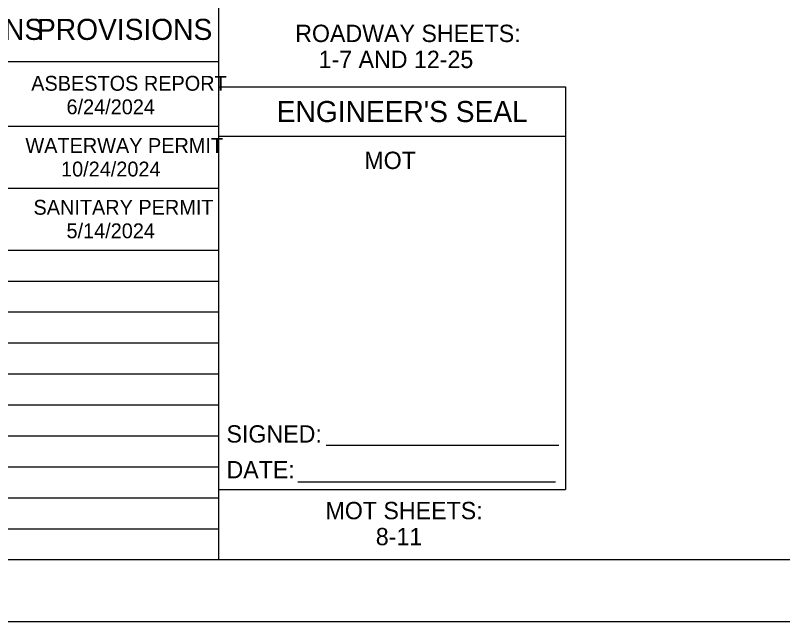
# Model space of a CAD drawing. Extents: x -4 to 116, y -17 to 29.
# Drawn here: x 70.44 to 76.64, y -14.61 to -9.71 of the extents above; entities that cross this region are included whole.
import ezdxf

# ---------------------------------------------------------------- set-up
doc = ezdxf.new("R2010")
doc.units = 0
for name, color, linetype in [('SH_Border', 7, 'Continuous'), ('SH_Cut_Line', 7, 'Continuous'), ('SH_Data', 7, 'Continuous'), ('SH_Text', 7, 'Continuous')]:
    doc.layers.add(name, color=color, linetype=linetype)

msp = doc.modelspace()

# ---------------------------------------------------------------- linework, layer by layer
at = {"layer": 'SH_Border'}
msp.add_lwpolyline([(49.9833, 6.8947), (81.9833, 6.8947), (81.9833, -14.1053), (49.9833, -14.1053)], close=True, dxfattribs=at)
at = {"layer": 'SH_Cut_Line'}
msp.add_lwpolyline([(48.4833, -14.6053), (82.4833, -14.6053), (82.4833, 7.3947), (48.4833, 7.3947)], close=True, dxfattribs=at)
at = {"layer": 'SH_Data'}
for p, q in [((72.0833, -10.5787), (72.0833, -7.3287)), ((72.0833, -14.1053), (72.0833, -9.3136)), ((58.6333, -10.0844), (72.0833, -10.0844)), ((72.0833, -10.2872), (74.8833, -10.2872)), ((74.8833, -10.2872), (74.8833, -13.5372)), ((58.6333, -10.6053), (72.0833, -10.6053)), ((72.0833, -10.6872), (74.8833, -10.6872)), ((72.0833, -14.1053), (72.0833, -10.8553)), ((58.6333, -11.1053), (72.0833, -11.1053)), ((58.6333, -11.6053), (72.0833, -11.6053)), ((58.6333, -11.8553), (72.0833, -11.8553)), ((58.6333, -12.1053), (72.0833, -12.1053)), ((58.6333, -12.3553), (72.0833, -12.3553)), ((58.6333, -12.6053), (72.0833, -12.6053)), ((58.6333, -12.8553), (72.0833, -12.8553)), ((58.6333, -13.1053), (72.0833, -13.1053)), ((58.6333, -13.3553), (72.0833, -13.3553)), ((72.0833, -13.5372), (74.8833, -13.5372)), ((58.6333, -13.6053), (72.0833, -13.6053)), ((58.6333, -13.8553), (72.0833, -13.8553))]:
    msp.add_line(p, q, dxfattribs=at)
at = {"layer": 'SH_Text'}
for p, q in [((72.9504, -13.1815), (74.8291, -13.1815)), ((72.7223, -13.4776), (74.8013, -13.4776))]:
    msp.add_line(p, q, dxfattribs=at)

# ---------------------------------------------------------------- texts
at = {"layer": 'SH_Data'}
for s, height, p in [('ROADWAY SHEETS: ', 0.14, (72.7, -9.9263)), ('1-7 AND 12-25', 0.14, (72.889, -10.1363)), ("ENGINEER'S SEAL", 0.17, (72.5508, -10.5722)), ('MOT', 0.14, (73.2583, -10.9513)), ('MOT SHEETS: ', 0.14, (72.9445, -13.7785)), ('8-11', 0.14, (73.3507, -13.9885))]:
    msp.add_text(s, height=height, dxfattribs=at).set_placement(p)
at = {"layer": 'SH_Text'}
for s, height, p in [('SPECIFICATIONS', 0.17, (68.7704, -9.909)), ('PROVISIONS', 0.17, (70.6156, -9.909)), ('ASBESTOS REPORT', 0.12, (70.5688, -10.3193)), ('6/24/2024', 0.12, (70.8535, -10.5093)), ('WATERWAY PERMIT', 0.12, (70.522, -10.8216)), ('10/24/2024', 0.12, (70.8096, -11.0116)), ('SANITARY PERMIT', 0.12, (70.5869, -11.3202)), ('5/14/2024', 0.12, (70.8535, -11.5102)), ('SIGNED: ', 0.14, (72.1453, -13.1598)), ('DATE:', 0.14, (72.1453, -13.4485))]:
    msp.add_text(s, height=height, dxfattribs=at).set_placement(p)

doc.saveas('drawing.dxf')
